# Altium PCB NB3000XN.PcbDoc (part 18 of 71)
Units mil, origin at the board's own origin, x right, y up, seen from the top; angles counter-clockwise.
Board outline 9527.56 x 6929.77 mil, 6 copper layers (Top Layer, GND+SHIELD, MidLayer1, MidLayer2, P2 - 3V3+5V0, Bottom Layer), stack 62.375 mil thick; 832 components, 1027 nets, 4655 pads, 4981 vias.
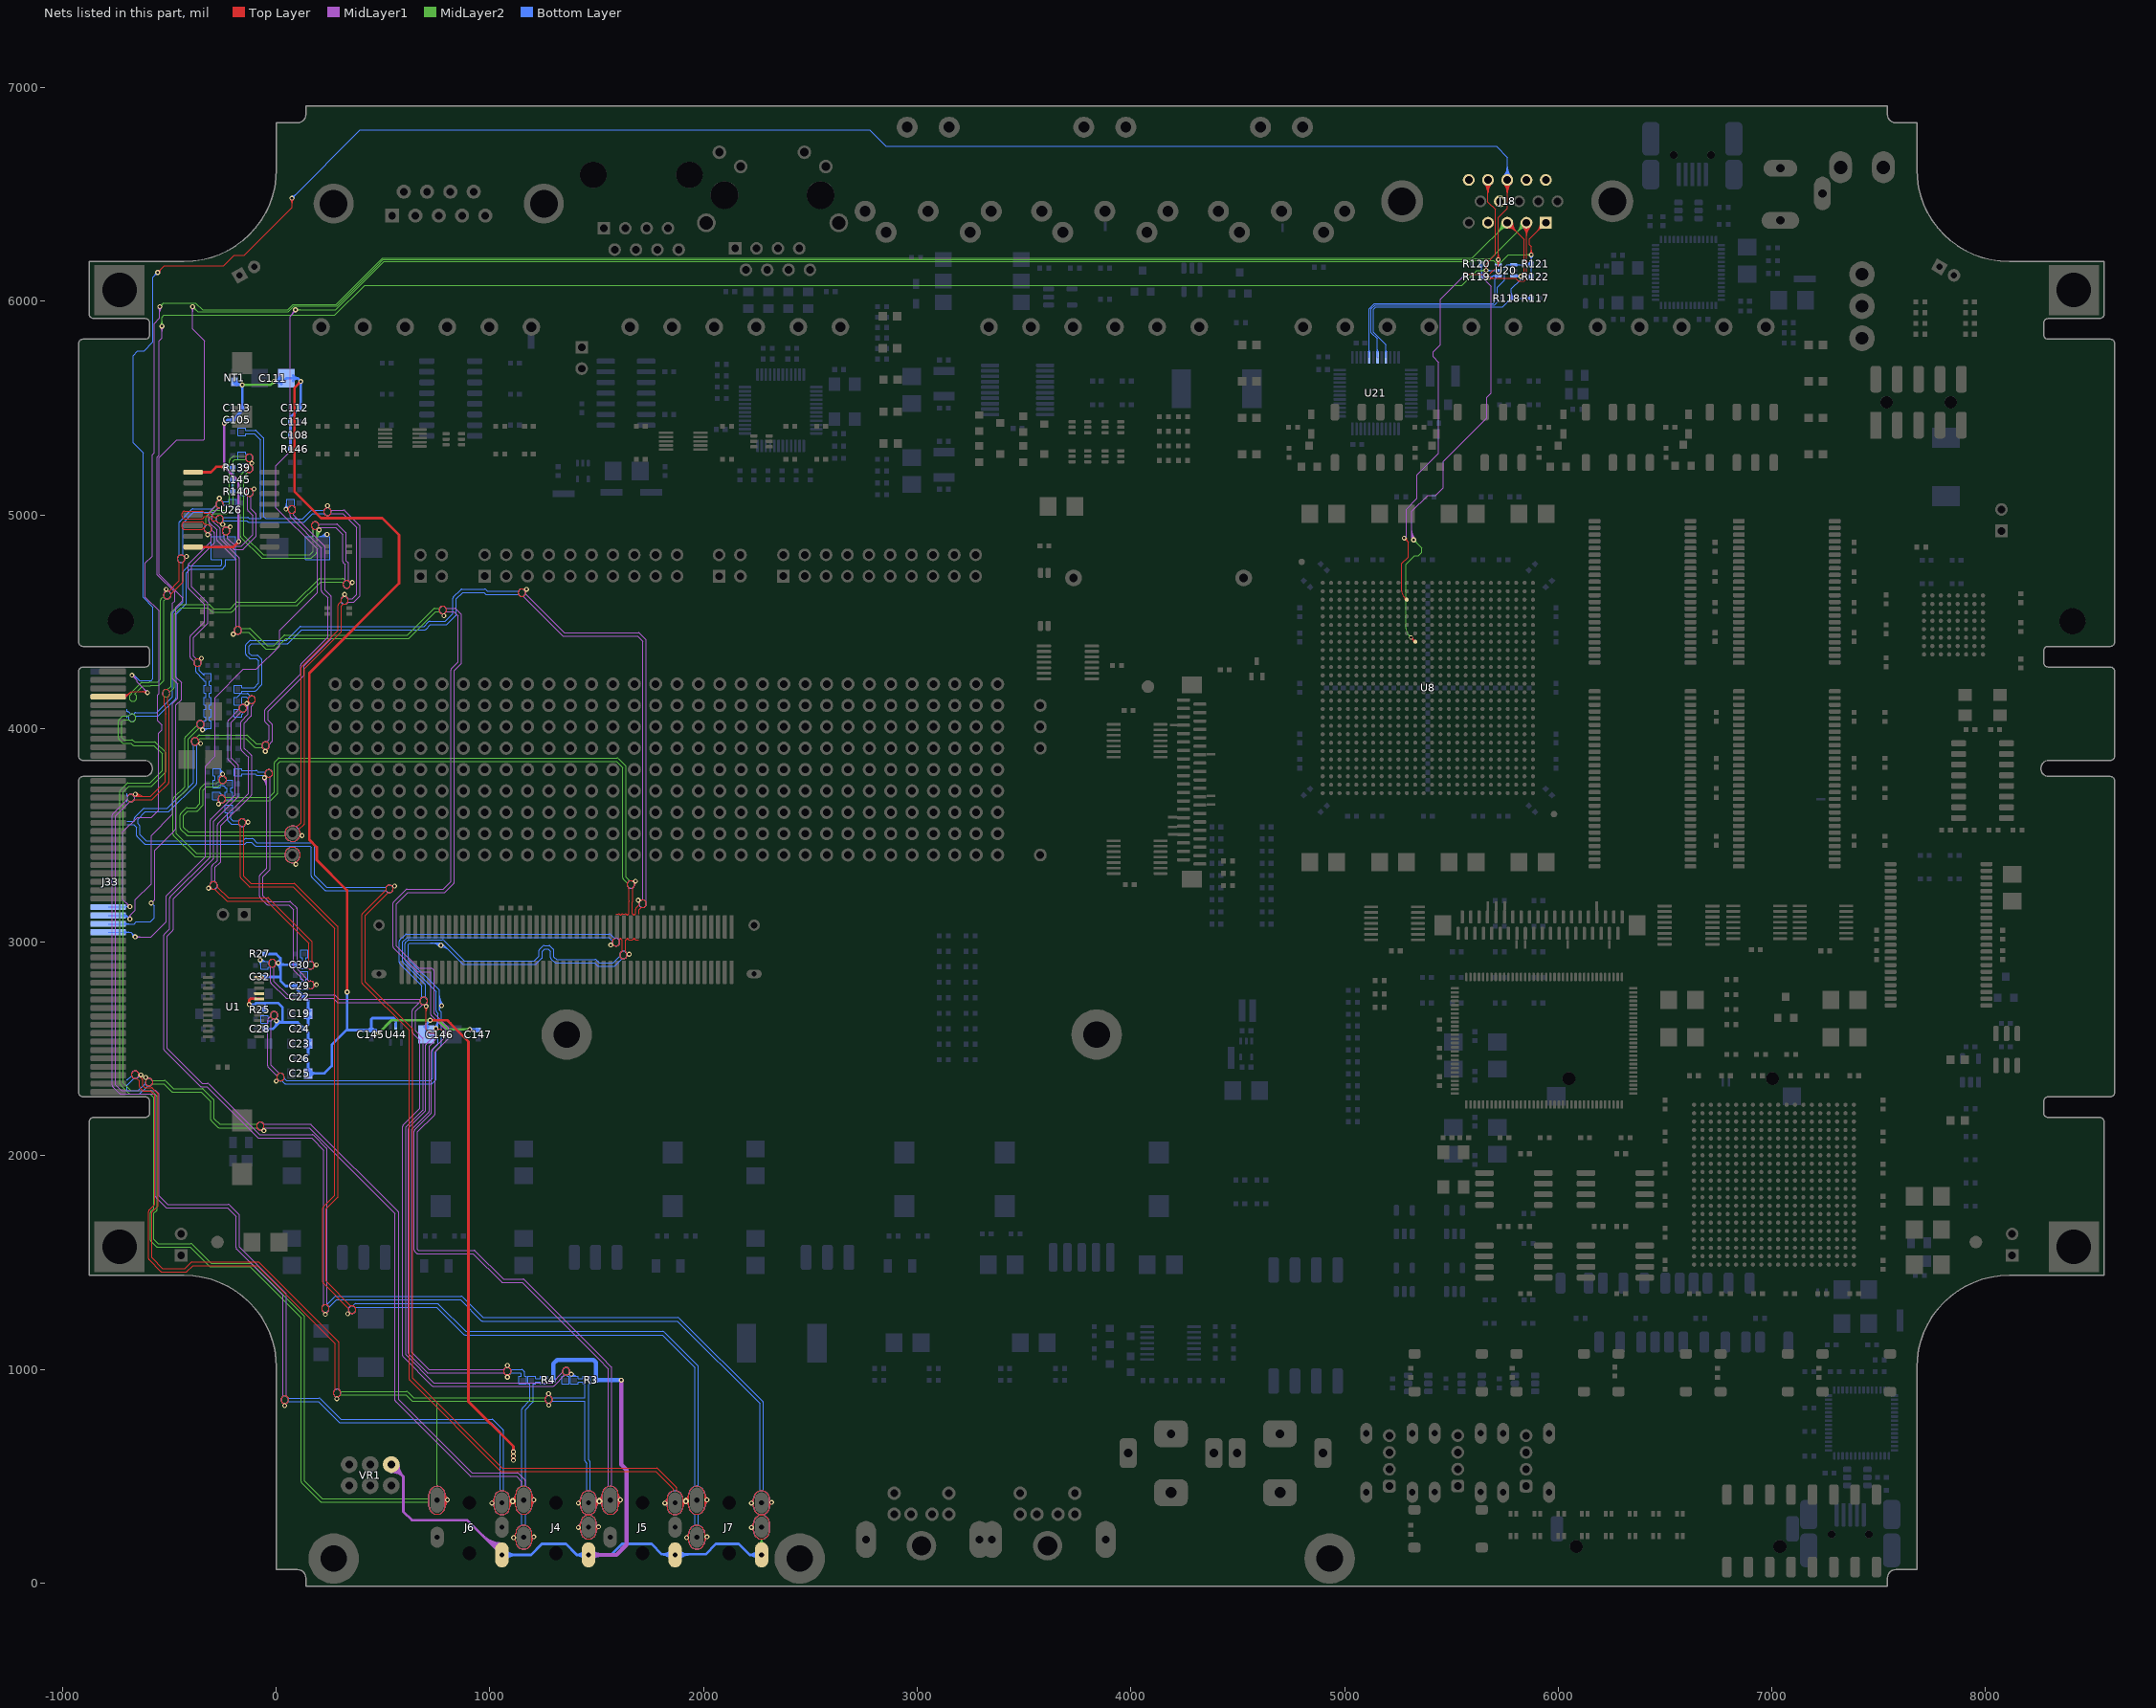
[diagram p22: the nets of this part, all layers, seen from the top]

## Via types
v1: diameter 23, hole 11.81, Top Layer to Bottom Layer, 3672 vias
v2: diameter 26, hole 11.81, Top Layer to Bottom Layer, 461 vias
v3: diameter 19, hole 11.81, Top Layer to Bottom Layer, tented both sides, 396 vias
v4: diameter 23.62, hole 11.81, Top Layer to Bottom Layer, 288 vias
v5: diameter 20, hole 11.81, Top Layer to Bottom Layer, 91 vias
v6: diameter 23, hole 11.81, Top Layer to Bottom Layer, tented both sides, 50 vias
v7: diameter 31, hole 11.81, Top Layer to Bottom Layer, 15 vias
v8: diameter 27.56, hole 11.81, Top Layer to Bottom Layer, tented both sides, 4 vias
v9: diameter 29, hole 11.81, Top Layer to Bottom Layer, 3 vias
v10: diameter 21, hole 11.81, Top Layer to Bottom Layer, 1 vias

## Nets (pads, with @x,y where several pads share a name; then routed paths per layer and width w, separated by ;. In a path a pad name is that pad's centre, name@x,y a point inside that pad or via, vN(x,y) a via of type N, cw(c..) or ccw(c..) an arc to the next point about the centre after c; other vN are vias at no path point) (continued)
ATE.VGA#.BLUE: J18.3 J33.B27 R117.1 R118.2 U20.3 U21.45 | length 12154.1
  Top Layer w4: J18.3@5761.68,6342.44 cw(c5761.68,6280.74) 5805.32,6324.37 cw(c5848.95,6368) J18.3@5787.24,6368 ; J18.3@5761.68,6346.44 cw(c5761.68,6294.39) 5798.49,6331.2 cw(c5835.29,6368) J18.3@5783.24,6368 ; J18.3@5761.68,6350.44 cw(c5761.68,6308.05) 5791.66,6338.02 cw(c5821.64,6368) J18.3@5779.24,6368 ; J18.3@5761.68,6354.44 cw(c5761.68,6321.71) 5784.83,6344.85 cw(c5807.98,6368) J18.3@5775.24,6368 ; J18.3@5761.68,6368 5840,6289.68 5840,6132.18 v1(5824.52,6116.71)
  MidLayer1 w4: v1@-694.31,3166.71 ccw(c-717.24,3166.71) -701.03,3182.93 ccw(c-684.81,3199.14) v1@-684.81,3176.21 ; v1@-690.31,3166.71 ccw(c-703.59,3166.71) -694.2,3176.1 ccw(c-684.81,3185.49) v1@-684.81,3172.21 ; v1(-684.81,3166.71) -718.14,3200.04 -718.14,3516.86 -650,3585 -583.94,3585 -551.48,3617.47 -551.48,3977.46 -534.5,3994.44 -534.5,4015.56 -555,4036.06 -555,4158.5 -549.19,4164.31 -549.19,4551.38 -612.81,4615 -612.81,4775 -580.14,4807.67 -580.14,5281.43 -571.52,5290.05 -571.52,5896.3 -545,5922.82 v4(-545,5975) ; v4@-551.94,5968.06 cw(c-568.69,5951.31) -545,5951.31 cw(c-521.31,5951.31) v4@-538.06,5968.06 ; v4@-549.11,5970.89 cw(c-559.03,5960.97) -545,5960.97 cw(c-530.97,5960.97) v4@-540.89,5970.89
  MidLayer2 w4: v4(-545,5975) -527.46,5992.54 -377.54,5992.54 -344.34,5959.34 53.28,5959.34 79.44,5985.5 280.5,5985.5 497.54,6202.54 5597.54,6202.54 5612.19,6217.19 5761.68,6366.68 J18.3@5761.68,6368 ; v4@-545,5980.81 ccw(c-545,5994.84) -535.08,5984.92 ccw(c-525.16,5975) v4@-539.19,5975 ; v4@-545,5984.81 ccw(c-545,6008.5) -528.25,5991.75 ccw(c-511.5,5975) v4@-535.19,5975 ; 5717.12,6322.12 ccw(c5671.25,6368) J18.3@5736.13,6368 ; 5720.3,6325.3 cw(c5761.68,6283.91) J18.3@5761.68,6342.44 ; 5723.95,6328.95 ccw(c5684.9,6368) J18.3@5740.13,6368 ; 5727.13,6332.13 cw(c5761.68,6297.57) J18.3@5761.68,6346.44 ; 5730.78,6335.78 ccw(c5698.56,6368) J18.3@5744.13,6368 ; 5733.95,6338.95 cw(c5761.68,6311.22) J18.3@5761.68,6350.44 ; 5737.61,6342.61 ccw(c5712.22,6368) J18.3@5748.13,6368 ; 5740.78,6345.78 cw(c5761.68,6324.88) J18.3@5761.68,6354.44
  Bottom Layer w4: J33.B27@-785.98,3164.67 -702.85,3164.67 -700.81,3166.71 ; v1@-693.15,3162.16 ccw(c-700.81,3157.98) -700.81,3166.71 ; v1@-693.15,3171.26 cw(c-700.81,3175.43) -700.81,3166.71 ; v1(-684.81,3166.71) -700.81,3166.71 ; U21.45@5191.38,5763.68 ccw(c5184.56,5770.51) 5194.21,5770.51 ccw(c5203.87,5770.51) U21.45@5197.04,5763.68 ; U21.45@5194.21,5737.32 5194.21,5795.79 5135,5855 5135,5962.37 5146.63,5974 5740.18,5974 R118.2@5781.18,6015 ; 5764.43,5998.25 cw(c5781.18,5981.5) R118.2@5781.18,6005.19 ; 5765.62,5999.44 ccw(c5750.55,6014.51) R118.2@5771.86,6014.51 ; R118.2@5771.26,6005.08 cw(c5781.18,5995.16) R118.2@5781.18,6009.19 ; R118.2@5772.45,6006.27 ccw(c5764.21,6014.51) R118.2@5775.86,6014.51 ; R118.2@5774.59,6022.08 ccw(c5758.68,6037.99) 5781.18,6037.99 ccw(c5803.68,6037.99) R118.2@5787.77,6022.08 ; R118.2@5777.42,6019.25 ccw(c5768.34,6028.33) 5781.18,6028.33 ccw(c5794.02,6028.33) R118.2@5784.94,6019.25 ; R118.2@5784.94,6011.24 cw(c5794.02,6002.16) 5794.02,6015 cw(c5794.02,6027.84) R118.2@5784.94,6018.76 ; R118.2@5787.77,6008.41 cw(c5803.68,5992.5) 5803.68,6015 cw(c5803.68,6037.5) R118.2@5787.77,6021.59 ; U20.3@5792.17,6118.82 v1@5815.19,6118.82 ; U20.3@5796.49,6118.82 cw(c5796.49,6088.68) v1@5817.81,6109.99 ; U20.3@5805.18,6114.67 cw(c5815.19,6104.68) v1@5815.19,6118.82 ; U20.3@5805.18,6122.97 ccw(c5815.19,6132.96) v1@5815.19,6118.82 ; U20.3@5806.15,6118.82 cw(c5806.15,6098.33) v1@5820.64,6112.82 ; U20.3@5806.69,6118.82 ccw(c5806.69,6134.55) v1@5817.81,6123.43 ; v1@5815.19,6118.71 5817.19,6116.71 v1(5824.52,6116.71) 5824.52,6101.71 5781.18,6058.36 R118.2@5781.18,6015 ; R117.1@5867.23,6008.41 ccw(c5851.32,5992.5) 5851.32,6015 ccw(c5851.32,6037.5) R117.1@5867.23,6021.59 ; R117.1@5870.06,6011.24 ccw(c5860.98,6002.16) 5860.98,6015 ccw(c5860.98,6027.84) R117.1@5870.06,6018.76 ; R117.1@5873.82,6015 R118.2@5781.18,6015
ATE.VGA#.GREEN: J18.2 J33.B29 R119.1 R120.2 U20.4 U21.41 | length 12545.8
  Top Layer w4: v1(5672.52,6108.37) 5801.63,6108.37 5815,6095 5840,6095 5851.84,6106.84 J18.2@5851.84,6368 ; v1@5676.41,6104.49 cw(c5685.8,6095.1) 5685.8,6108.37 cw(c5685.8,6121.65) v1@5676.41,6112.26 ; v1@5679.24,6101.66 cw(c5695.46,6085.44) 5695.46,6108.37 cw(c5695.46,6131.31) v1@5679.24,6115.09 ; J18.2@5833.77,6349.93 cw(c5790.14,6306.3) 5851.84,6306.3 cw(c5913.55,6306.3) J18.2@5869.92,6349.93 ; J18.2@5836.6,6352.76 cw(c5799.79,6315.95) 5851.84,6315.95 cw(c5903.89,6315.95) J18.2@5867.09,6352.76 ; J18.2@5839.43,6355.58 cw(c5809.45,6325.61) 5851.84,6325.61 cw(c5894.23,6325.61) J18.2@5864.26,6355.58 ; J18.2@5842.25,6358.41 cw(c5819.11,6335.27) 5851.84,6335.27 cw(c5884.58,6335.27) J18.2@5861.43,6358.41
  MidLayer1 w4: v1(-584.81,3183.37) -569,3199.18 -569,3217.77 -568.98,3429.56 -487.44,3511.1 -468.81,3529.73 -468.81,4109.94 -444,4134.75 -444,4170 -444,4215.25 -468.81,4240.06 -468.81,4566.44 -437.5,4597.75 -437.5,4612.25 -548.14,4722.89 -548.14,5268.17 -464.75,5351.56 -339.03,5351.56 -335.52,5355.08 -335.52,5815.05 -391.48,5871.01 v1(-391.48,5975.04) ; v1@-398.19,5968.32 cw(c-414.41,5952.11) -391.48,5952.11 cw(c-368.54,5952.11) v1@-384.76,5968.32 ; v1@-395.36,5971.15 cw(c-404.75,5961.76) -391.48,5961.76 cw(c-378.2,5961.76) v1@-387.59,5971.15
  MidLayer2 w4: v1@-391.48,5965.54 cw(c-391.48,5942.61) -375.26,5958.82 cw(c-359.04,5975.04) v1@-381.98,5975.04 ; v1@-391.48,5969.54 cw(c-391.48,5956.26) -382.09,5965.65 cw(c-372.7,5975.04) v1@-385.98,5975.04 ; v1(-391.48,5975.04) -367.77,5951.34 56.59,5951.34 82.75,5977.5 283.81,5977.5 472.5,6166.19 500.85,6194.54 5600.85,6194.54 5606.35,6200.04 5683.88,6200.04 J18.2@5851.84,6368 ; J18.2@5826.28,6368 cw(c5764.58,6368) 5808.21,6324.37 cw(c5851.84,6280.74) J18.2@5851.84,6342.44 ; J18.2@5830.28,6368 cw(c5778.23,6368) 5815.04,6331.19 cw(c5851.84,6294.4) J18.2@5851.84,6346.44 ; J18.2@5834.28,6368 cw(c5791.89,6368) 5821.87,6338.02 cw(c5851.84,6308.05) J18.2@5851.84,6350.44 ; J18.2@5838.28,6368 cw(c5805.55,6368) 5828.7,6344.85 cw(c5851.84,6321.71) J18.2@5851.84,6354.44
  Bottom Layer w4: J33.B29@-785.98,3085.93 -663.92,3085.93 -654.72,3095.13 -589.54,3095.13 -570.41,3114.27 -570.41,3168.97 v1(-584.81,3183.37) ; J33.B29@-711.58,3080.43 cw(c-698.3,3067.15) -698.3,3085.93 cw(c-698.3,3104.71) J33.B29@-711.58,3091.43 ; J33.B29@-708.76,3077.6 cw(c-688.65,3057.49) -688.65,3085.93 cw(c-688.65,3114.37) J33.B29@-708.76,3094.26 ; U21.41@5112.64,5763.68 ccw(c5105.82,5770.51) 5115.47,5770.51 ccw(c5125.13,5770.51) U21.41@5118.3,5763.68 ; U21.41@5115.47,5737.32 5115.47,5965.47 5140,5990 5695,5990 5705,6000 5705,6104.49 U20.4@5719.33,6118.82 5718.15,6120 5695,6120 ; R119.1@5634.59,6122.08 ccw(c5618.68,6137.99) 5641.18,6137.99 ccw(c5663.68,6137.99) R119.1@5647.77,6122.08 ; R120.2@5634.59,6167.92 cw(c5618.68,6152.01) 5641.18,6152.01 cw(c5663.68,6152.01) R120.2@5647.77,6167.92 ; R119.1@5637.42,6119.25 ccw(c5628.34,6128.33) 5641.18,6128.33 ccw(c5654.02,6128.33) R119.1@5644.94,6119.25 ; R120.2@5637.42,6170.75 cw(c5628.34,6161.67) 5641.18,6161.67 cw(c5654.02,6161.67) R120.2@5644.94,6170.75 ; R120.2@5641.18,6175 R119.1@5641.18,6115 5647.81,6108.37 v1(5672.52,6108.37) ; R119.1@5642.23,6115.31 ccw(c5656.3,6126.11) 5656.3,6108.37 ; R119.1@5645.4,6117.75 ccw(c5664.41,6132.34) v1@5664.41,6108.37 ; R119.1@5648.57,6120.18 ccw(c5672.52,6138.57) v1(5672.52,6108.37) ; v1@5665.81,6101.66 ccw(c5649.59,6085.44) 5649.59,6108.37 ccw(c5649.59,6131.31) v1@5665.81,6115.09 ; v1@5668.64,6104.49 ccw(c5659.25,6095.1) 5659.25,6108.37 ccw(c5659.25,6121.65) v1@5668.64,6112.26 ; v1@5673.18,6109.72 ccw(c5678.48,6120.63) 5687.06,6112.06 ; v1@5674.93,6113.32 ccw(c5681.08,6125.98) 5691.03,6116.03 ; v1@5676.68,6116.92 ccw(c5683.68,6131.32) 5695,6120 ; 5699.14,6120 ccw(c5699.14,6130.15) U20.4@5706.32,6122.97 ; U20.4@5706.04,6114.97 ccw(c5695,6105.38) 5695,6120 ; v1(5672.52,6108.37) 5683.37,6108.37 5695,6120
ATE.VGA#.HSYNC: J18.13 J33.A4 U8.C11 U20.6 | length 13202.8
  Top Layer w4: J33.A4@-785.98,4148.92 -702.59,4148.92 ; J33.A4@-717.72,4144.75 ccw(c-714.86,4163.57) -701.41,4150.11 ; J33.A4@-717.12,4148.71 ccw(c-713.39,4173.29) -695.81,4155.71 ; J33.A4@-716.52,4152.66 ccw(c-711.92,4183.01) -690.21,4161.3 ; J33.A4@-715.92,4156.62 ccw(c-710.44,4192.73) -684.62,4166.9 ; J33.A4@-715.32,4160.57 ccw(c-708.97,4202.45) -679.02,4172.5 ; J33.A4@-705.55,4146.52 cw(c-702.59,4145.9) -702.59,4148.92 ; J33.A4@-705.55,4151.33 ccw(c-702.59,4151.95) -702.59,4148.92 ; -635.21,4172.5 cw(c-635.21,4135.48) v1@-609.03,4161.66 ; -625.55,4172.5 cw(c-625.55,4145.14) v1@-606.2,4164.49 ; -615.89,4172.5 cw(c-615.89,4154.79) v1@-603.37,4167.31 ; -615.29,4172.5 ccw(c-615.29,4181.35) v1@-609.03,4175.09 ; v1(-602.31,4168.37) -601.48,4168.37 -605.6,4172.5 -679.02,4172.5 -702.59,4148.92 ; v1(-555,6135) -523.29,6166.71 -245.92,6166.71 -197.15,6215.48 -149.52,6215.48 73.52,6438.52 v1(73.52,6482.71) ; v1@-555,6140.5 ccw(c-555,6153.78) -545.61,6144.39 ccw(c-536.22,6135) v1@-549.5,6135 ; v1@-555,6144.5 ccw(c-555,6167.43) -538.78,6151.22 ccw(c-522.57,6135) v1@-545.5,6135 ; v1@66.81,6475.99 cw(c50.59,6459.77) 73.52,6459.77 cw(c96.46,6459.77) v1@80.24,6475.99 ; v1@69.64,6478.82 cw(c60.25,6469.43) 73.52,6469.43 cw(c86.8,6469.43) v1@77.41,6478.82 ; v1@5279.52,4881.87 cw(c5279.52,4858.94) 5295.74,4875.16 cw(c5311.96,4891.37) v1@5289.02,4891.37 ; v1@5279.52,4885.87 cw(c5279.52,4872.6) 5288.91,4881.99 cw(c5298.3,4891.37) v1@5285.02,4891.37 ; v1(5279.52,4891.37) 5298.02,4872.87 5298.02,4803.13 5267.71,4772.82 ; U8.C11@5284.23,4603.39 ccw(c5266.51,4603.39) 5279.04,4615.92 ; U8.C11@5291.57,4610.73 cw(c5291.57,4628.45) 5279.04,4615.92 ; v1(5565.52,6126.37) 5678.52,6126.37 5719.19,6167.04 v1(5719.19,6195.04) ; v1@5569.41,6122.49 cw(c5578.8,6113.1) 5578.8,6126.37 cw(c5578.8,6139.65) v1@5569.41,6130.26 ; v1@5572.24,6119.66 cw(c5588.46,6103.44) 5588.46,6126.37 cw(c5588.46,6149.31) v1@5572.24,6133.09 ; v1@5712.47,6188.32 cw(c5696.26,6172.11) 5719.19,6172.11 cw(c5742.13,6172.11) v1@5725.91,6188.32 ; v1@5712.47,6201.76 ccw(c5696.26,6217.98) 5719.19,6217.98 ccw(c5742.13,6217.98) v1@5725.91,6201.76 ; v1@5715.3,6191.15 cw(c5705.91,6181.76) 5719.19,6181.76 cw(c5732.47,6181.76) v1@5723.08,6191.15 ; v1@5715.3,6198.93 ccw(c5705.91,6208.32) 5719.19,6208.32 ccw(c5732.47,6208.32) v1@5723.08,6198.93 ; v1@5723.52,6199.37 v1(5719.19,6195.04) ; J18.13@5743.61,6549.93 cw(c5699.98,6506.29) 5761.69,6506.29 cw(c5823.39,6506.3) J18.13@5779.76,6549.93 ; J18.13@5746.44,6552.76 cw(c5709.64,6515.95) 5761.69,6515.95 cw(c5813.73,6515.95) J18.13@5776.93,6552.76 ; J18.13@5749.27,6555.58 cw(c5719.29,6525.61) 5761.69,6525.61 cw(c5804.08,6525.61) J18.13@5774.1,6555.58 ; J18.13@5752.1,6558.41 cw(c5728.95,6535.27) 5761.69,6535.27 cw(c5794.42,6535.27) J18.13@5771.27,6558.41 ; J18.13@5761.68,6568 5761.69,6435 5719.19,6392.5 v1(5719.19,6195.04) ; 5267.71,4720 5267.71,4724.74 5267.71,4772.82 ; 5267.71,4720 5267.71,4772.81 ; 5267.71,4720 5267.71,4710 5267.71,4643.27 ccw(c5306.39,4643.27) 5279.04,4615.92
  MidLayer1 w4: v1@-675,4240.5 cw(c-675,4217.56) -658.78,4233.78 cw(c-642.57,4250) v1@-665.5,4250 ; v1@-675,4244.5 cw(c-675,4231.22) -665.61,4240.61 cw(c-656.22,4250) v1@-669.5,4250 ; v1(-675,4250) -650.69,4225.69 -650.69,4217.59 v1@-602.31,4169.21 ; -619.12,4186.02 cw(c-636.76,4168.37) v1@-611.81,4168.37 ; -617.1,4184 ccw(c-602.31,4198.79) v1@-602.31,4177.87 ; -612.29,4179.19 cw(c-623.11,4168.37) v1@-607.81,4168.37 ; -610.27,4177.17 ccw(c-602.31,4185.14) v1@-602.31,4173.87 ; v1(5279.52,4891.37) 5289.52,4901.37 5289.52,5027 5340.19,5077.67 5340.19,5188.73 5440.19,5288.73 5440.19,5582.37 5440.19,5715 5415.19,5740 5415.19,5764.04 5448.52,5797.37 5448.52,6009.37 v1(5565.52,6126.37) ; v1@5556.02,6126.37 cw(c5533.09,6126.37) 5549.31,6110.16 cw(c5565.52,6093.94) v1@5565.52,6116.87 ; v1@5560.02,6126.37 cw(c5546.75,6126.37) 5556.14,6116.99 cw(c5565.52,6107.6) v1@5565.52,6120.87 ; v1@-602.31,4169.21 v1(-602.31,4168.37) -601.48,4168.37 v1@-602.31,4169.21
  Bottom Layer w4: v1@-675,4240.5 cw(c-675,4193.67) -641.88,4226.78 ; v1@-675,4244.5 cw(c-675,4207.32) -648.71,4233.61 ; v1@-675,4248.5 cw(c-675,4220.98) -655.54,4240.44 ; v1(-675,4250) -665.1,4250 -640.1,4225 -585,4225 -576.48,4233.52 -576.48,4567.02 -623,4613.54 -623,5291.69 -670,5338.69 -670,5746.12 -648.12,5768 -618.31,5768 -576.48,5809.84 -576.48,6113.52 v1(-555,6135) ; v1@-675,4252.5 cw(c-675,4234.64) -662.37,4247.27 ; v1@-564.5,6135 cw(c-587.44,6135) -571.22,6118.78 cw(c-555,6102.56) v1@-555,6125.5 ; v1@-560.5,6135 cw(c-573.78,6135) -564.39,6125.61 cw(c-555,6116.22) v1@-555,6129.5 ; v1(73.52,6482.71) 392.82,6802 2776.69,6802 2853.65,6725.04 5709.96,6725.04 5761.68,6673.31 J18.13@5761.68,6568 ; v1@73.52,6488.21 ccw(c73.52,6501.49) 82.91,6492.1 ccw(c92.3,6482.71) v1@79.02,6482.71 ; v1@73.52,6492.21 ccw(c73.52,6515.14) 89.74,6498.93 ccw(c105.96,6482.71) v1@83.02,6482.71 ; v1@5712.47,6188.32 cw(c5695.91,6171.76) U20.6@5719.33,6171.76 ; U20.6@5715.18,6174.15 ccw(c5705.15,6184.18) 5719.33,6184.18 ccw(c5733.51,6184.18) U20.6@5723.49,6174.15 ; v1@5715.3,6191.15 cw(c5705.57,6181.42) 5719.33,6181.42 ; v1(5719.19,6195.04) 5719.33,6194.9 U20.6@5719.33,6170 ; U20.6@5719.33,6172.45 cw(c5741.78,6172.45) v1@5725.91,6188.32 ; 5719.33,6182.11 cw(c5732.12,6182.11) v1@5723.08,6191.15 ; J18.13@5743.61,6586.07 ccw(c5699.98,6629.7) 5761.69,6629.7 ccw(c5823.39,6629.7) J18.13@5779.76,6586.07 ; J18.13@5746.44,6583.24 ccw(c5709.64,6620.05) 5761.68,6620.05 ccw(c5813.73,6620.05) J18.13@5776.93,6583.24 ; J18.13@5749.27,6580.42 ccw(c5719.29,6610.39) 5761.68,6610.39 ccw(c5804.08,6610.39) J18.13@5774.1,6580.42 ; J18.13@5752.1,6577.59 ccw(c5728.95,6600.73) 5761.68,6600.73 ccw(c5794.42,6600.73) J18.13@5771.27,6577.59
ATE.VGA#.ID0: J18.11
ATE.VGA#.ID1/SDA/DDC: J18.12
ATE.VGA#.ID2: J18.4
ATE.VGA#.ID3/SCL/DDC: J18.15
ATE.VGA#.KEY: J18.9
ATE.VGA#.RED: J18.1 J33.B30 R121.2 R122.2 U20.1 U21.43 | length 12038.7
  Top Layer w4: v1@5867.14,6223.76 ccw(c5850.92,6239.98) 5873.86,6239.98 ccw(c5896.79,6239.98) v1@5880.57,6223.76 ; v1@5869.97,6220.93 ccw(c5860.58,6230.32) 5873.86,6230.32 ccw(c5887.14,6230.32) v1@5877.75,6220.93 ; v1(5873.86,6217.04) 5873.86,6256.14 5865,6265 5865,6291 J18.1@5942,6368 ; J18.1@5916.44,6368 cw(c5854.74,6368) 5898.37,6324.37 cw(c5942,6280.74) J18.1@5942,6342.44 ; J18.1@5920.44,6368 cw(c5868.39,6368) 5905.2,6331.2 cw(c5942,6294.39) J18.1@5942,6346.44 ; J18.1@5924.44,6368 cw(c5882.05,6368) 5912.02,6338.02 cw(c5942,6308.05) J18.1@5942,6350.44 ; J18.1@5928.44,6368 cw(c5895.71,6368) 5918.85,6344.85 cw(c5942,6321.71) J18.1@5942,6354.44
  MidLayer1 w4: v1(-659.81,3025.04) -586.02,3025.04 -521,3090.06 -521,3090.31 -515.5,3095.81 -515.5,3216.82 -332,3400.32 -332,3823.31 -285.23,3870.09 -285.23,4006.77 -287,4008.55 -287,4144.87 -153.87,4278 -93.16,4278 15.19,4386.35 15.19,4460.19 192,4637 192,4840.65 -1.48,5034.13 -1.48,5230.39 65.19,5297.06 65.19,5930 v1@92.6,5957.4 ; v1@-655.92,3021.15 cw(c-646.53,3011.76) -646.53,3025.04 cw(c-646.53,3038.32) v1@-655.92,3028.93 ; v1@-653.09,3018.32 cw(c-636.87,3002.11) -636.87,3025.04 cw(c-636.87,3047.98) v1@-653.09,3031.76 ; 70.11,5934.92 ccw(c45.03,5960) v1@80.5,5960 ; 76.94,5941.75 ccw(c58.69,5960) v1@84.5,5960 ; 82.64,5947.45 cw(c90,5940.1) v1@90,5950.5 ; 83.77,5948.58 ccw(c72.35,5960) v1@88.5,5960
  MidLayer2 w4: v1(90,5960) 277.63,5960 504.17,6186.54 5604.17,6186.54 5609.34,6191.71 5697.77,6191.71 5711.94,6177.54 5726.44,6177.54 5765.94,6217.04 v1(5873.86,6217.04) ; v1@93.89,5956.11 cw(c103.28,5946.72) 103.28,5960 cw(c103.28,5973.28) v1@93.89,5963.89 ; v1@96.72,5953.28 cw(c112.93,5937.06) 112.93,5960 cw(c112.93,5982.93) v1@96.72,5966.72 ; v1@5867.14,6210.32 ccw(c5850.92,6194.11) 5850.92,6217.04 ccw(c5850.92,6239.98) v1@5867.14,6223.76 ; v1@5869.97,6213.15 ccw(c5860.58,6203.76) 5860.58,6217.04 ccw(c5860.58,6230.32) v1@5869.97,6220.93
  Bottom Layer w4: J33.B30@-785.98,3046.56 -681.33,3046.56 v1(-659.81,3025.04) ; J33.B30@-711.58,3041.06 cw(c-698.3,3027.78) -698.3,3046.56 cw(c-698.3,3065.34) J33.B30@-711.58,3052.06 ; J33.B30@-708.76,3038.23 cw(c-688.65,3018.12) -688.65,3046.56 cw(c-688.65,3075) J33.B30@-708.76,3054.89 ; v1@-669.31,3025.04 ccw(c-692.24,3025.04) -676.03,3041.26 ccw(c-659.81,3057.48) v1@-659.81,3034.54 ; v1@-665.31,3025.04 ccw(c-678.59,3025.04) -669.2,3034.43 ccw(c-659.81,3043.82) v1@-659.81,3030.54 ; 5152.89,5775.23 ccw(c5169.22,5775.23) U21.43@5157.67,5763.68 ; U21.43@5154.84,5737.32 5152.89,5739.28 5152.89,5825 5125,5852.89 5125,5963.69 5143.31,5982 5702,5982 5715,5995 5715,6065 5750,6100 5750,6160 5760,6170 U20.1@5792.17,6170 5868.82,6170 R121.2@5873.82,6175 ; U20.1@5779.16,6165.85 ccw(c5769.13,6155.82) 5769.13,6170 ccw(c5769.13,6184.18) U20.1@5779.16,6174.15 ; U20.1@5805.18,6165.85 cw(c5815.21,6155.82) 5815.21,6170 cw(c5815.21,6184.18) U20.1@5805.18,6174.15 ; 5840.44,6170 ccw(c5840.44,6207.89) R121.2@5867.23,6181.1 ; 5850.09,6170 ccw(c5850.09,6198.23) R121.2@5870.06,6178.27 ; 5859.75,6170 ccw(c5859.75,6188.57) R121.2@5872.89,6175.44 ; 5862.2,6170 cw(c5862.2,6162.89) 5867.23,6167.92 cw(c5851.32,6152.01) 5873.82,6152.01 cw(c5896.32,6152.01) R121.2@5880.41,6167.92 ; v1@5867.14,6210.32 cw(c5850.92,6194.11) 5873.86,6194.11 cw(c5896.79,6194.11) v1@5880.57,6210.32 ; R122.2@5867.23,6122.08 ccw(c5851.32,6137.99) 5873.82,6137.99 ccw(c5896.32,6137.99) R122.2@5880.41,6122.08 ; R121.2@5867.23,6182.08 ccw(c5851.23,6198.08) 5873.86,6198.08 ; v1@5869.97,6213.15 cw(c5860.58,6203.76) 5873.86,6203.76 cw(c5887.14,6203.76) v1@5877.75,6213.15 ; R122.2@5870.06,6119.25 ccw(c5860.98,6128.33) 5873.82,6128.33 ccw(c5886.66,6128.33) R122.2@5877.58,6119.25 ; R121.2@5870.06,6170.75 cw(c5860.98,6161.67) 5873.82,6161.67 cw(c5886.66,6161.67) R121.2@5877.58,6170.75 ; R121.2@5870.06,6179.25 ccw(c5860.89,6188.43) 5873.86,6188.43 ; R122.2@5873.82,6115 R121.2@5873.82,6175 ; 5873.86,6188.24 ccw(c5886.57,6188.24) R121.2@5877.58,6179.25 ; 5873.86,6197.9 ccw(c5896.22,6197.9) R121.2@5880.41,6182.08 ; v1(5873.86,6217.04) 5873.86,6175.04 R121.2@5873.82,6175
ATE.VGA#.VSYNC: J18.14 J33.B28 U8.H12 U20.5 | length 13007.6
  Top Layer w4: v3(5311.26,4426.22) U8.H12@5330.94,4406.54 ; U8.H12@5323.44,4406.54 ccw(c5305.34,4406.54) 5318.14,4419.34 ccw(c5330.94,4432.14) U8.H12@5330.94,4414.04 ; U8.H12@5323.6,4406.54 ccw(c5305.88,4406.54) 5318.41,4419.07 ccw(c5330.94,4431.6) U8.H12@5330.94,4413.88 ; J18.14@5653.45,6549.93 cw(c5609.82,6506.29) 5671.53,6506.29 cw(c5733.23,6506.3) J18.14@5689.6,6549.93 ; v1@5656.14,6151.43 ccw(c5639.92,6167.64) 5662.86,6167.64 ccw(c5685.79,6167.64) v1@5669.57,6151.43 ; J18.14@5656.28,6552.76 cw(c5619.48,6515.95) 5671.53,6515.95 cw(c5723.57,6515.95) J18.14@5686.77,6552.76 ; v1@5658.97,6148.6 ccw(c5649.58,6157.99) 5662.86,6157.99 ccw(c5676.14,6157.99) v1@5666.75,6148.6 ; J18.14@5659.11,6555.58 cw(c5629.13,6525.61) 5671.53,6525.61 cw(c5713.92,6525.61) J18.14@5683.94,6555.58 ; J18.14@5661.94,6558.41 cw(c5638.79,6535.26) 5671.53,6535.26 cw(c5704.26,6535.27) J18.14@5681.12,6558.41 ; v1(5662.86,6144.71) 5662.86,6175 5706.86,6219 5706.86,6429.71 5671.53,6465.04 J18.14@5671.53,6568 ; 5324.06,4413.42 cw(c5336.87,4426.22) 5318.76,4426.22 ccw(c5336.87,4426.22) 5324.06,4413.42 ; 5324.06,4413.42 ccw(c5311.26,4400.61) 5311.26,4418.72 cw(c5311.26,4400.61) 5324.06,4413.42
  MidLayer1 w4: v1@-689.65,3116.55 ccw(c-694.68,3125.04) -684.81,3125.04 ; v1(-684.81,3108.37) -684.81,3125.04 ; v1@-679.97,3116.55 cw(c-674.94,3125.04) -684.81,3125.04 ; v1@-541.53,5876.66 cw(c-557.74,5860.44) -534.81,5860.44 cw(c-511.87,5860.44) v1@-528.09,5876.66 ; v1@-538.7,5879.49 cw(c-548.09,5870.1) -534.81,5870.1 cw(c-521.53,5870.1) v1@-530.92,5879.49 ; v1(-534.81,5883.37) -534.81,5827.75 -544,5818.56 -547.52,5815.05 -547.52,5280.11 -556.14,5271.48 -556.14,4719.58 -475,4638.43 -475,4596.31 -484.81,4586.5 -484.81,4233.43 -460,4208.62 -460,4141.38 -484.81,4116.57 -484.81,3600.04 -585,3499.85 -585,3272.79 -659.81,3197.98 -659.81,3150.04 -684.81,3125.04 ; 5315.19,4897.46 ccw(c5337.61,4897.46) v1@5321.76,4881.61 ; 5315.19,4907.12 ccw(c5347.27,4907.12) v1@5324.58,4884.44 ; 5315.19,4916.77 ccw(c5356.92,4916.77) v1@5327.41,4887.26 ; 5315.19,4926.43 ccw(c5366.58,4926.43) v1@5330.24,4890.09 ; v1(5323.52,4883.37) 5315.19,4891.71 5315.19,5016.71 5390.19,5091.71 5426.71,5091.71 5462.5,5127.5 5462.5,5250.33 5666.19,5454.02 5666.19,5551.45 5686,5571.26 5686,6069 5650,6105 5650,6131.85 v1(5662.86,6144.71)
  MidLayer2 w4: v1@-541.53,5890.09 ccw(c-557.74,5906.31) -534.81,5906.31 ccw(c-511.87,5906.31) v1@-528.09,5890.09 ; v1@-538.7,5887.26 ccw(c-548.09,5896.65) -534.81,5896.65 ccw(c-521.53,5896.65) v1@-530.92,5887.26 ; v1(-534.81,5883.37) -534.81,5925.19 -524.66,5935.34 78.6,5935.34 79.44,5934.5 274.76,5934.5 415.3,6075.04 5550,6075.04 5619.67,6144.71 v1(5662.86,6144.71) ; 5287.4,4699.16 5287.4,4640.9 ; v3@5303.79,4426.87 ccw(c5285.75,4428.45) 5299.62,4440.09 ; v3@5311.91,4433.69 cw(c5313.49,4451.73) 5299.62,4440.09 ; v1@5323.52,4873.87 cw(c5323.52,4850.94) 5339.74,4867.16 cw(c5355.96,4883.37) v1@5333.02,4883.37 ; v1@5323.52,4877.87 cw(c5323.52,4864.6) 5332.91,4873.99 cw(c5342.3,4883.37) v1@5329.02,4883.37 ; v1(5323.52,4883.37) 5362.52,4844.37 5362.52,4827.52 5362.5,4825 5347.07,4809.56 5327.03,4809.56 5287.4,4769.93 5287.4,4720 5287.4,4710 5287.4,4640.9 ; v1@5656.14,6137.99 ccw(c5639.92,6121.77) 5639.92,6144.71 ccw(c5639.92,6167.64) v1@5656.14,6151.43 ; v1@5658.97,6140.82 ccw(c5649.58,6131.43) 5649.58,6144.71 ccw(c5649.58,6157.99) v1@5658.97,6148.6 ; 5287.4,4640.9 5287.4,4582.64 5287.4,4563.22 5287.4,4489.1 5287.4,4469.6 ccw(c5329.13,4469.6) 5299.62,4440.09
  Bottom Layer w4: J33.B28@-785.98,3125.3 -701.74,3125.3 ; J33.B28@-717.65,3129.48 cw(c-714.82,3108.65) -699.95,3123.52 ; J33.B28@-717.11,3125.52 cw(c-713.45,3098.61) -694.25,3117.81 ; J33.B28@-716.57,3121.56 cw(c-712.09,3088.57) v1@-688.55,3112.11 ; J33.B28@-716.04,3117.59 cw(c-710.72,3078.53) v1@-682.84,3106.41 ; J33.B28@-705.71,3122.26 cw(c-701.74,3121.19) -701.74,3125.3 ; J33.B28@-705.71,3128.35 ccw(c-701.74,3129.41) -701.74,3125.3 ; v1@-694.31,3108.37 ccw(c-717.24,3108.37) -701.03,3124.59 ccw(c-684.81,3140.81) v1@-684.81,3117.87 ; v1@-690.31,3108.37 ccw(c-703.59,3108.37) -694.2,3117.76 ccw(c-684.81,3127.15) v1@-684.81,3113.87 ; v1(-684.81,3108.37) -701.74,3125.3 ; v1(5662.86,6144.71) 5678.86,6144.71 ; v1@5671.2,6140.16 cw(c5678.86,6135.98) 5678.86,6144.71 ; v1@5671.2,6149.26 ccw(c5678.86,6153.43) 5678.86,6144.71 ; U20.5@5706.32,6140.26 ccw(c5696.29,6130.23) 5696.29,6144.41 ccw(c5696.29,6158.59) U20.5@5706.32,6148.56 ; U20.5@5719.33,6144.41 5679.16,6144.41 5678.86,6144.71
AUDIO_CODEC.MUTEA: U1.21
AUDIO_CODEC.MUTEB: U1.24
AUGND: C19.2 C22.2 C23.2 C24.1 C25.2 C26.2 C28.2 C29.2 C30.2 C32.2 C105.1 C108.2 C111.2 C112.1 C113.1 C114.1 C145.1 C146.2 C147.1 J4.1 J5.1 J6.1 J7.1 NT1.1 R3.1 R4.1 R25.1 R27.1 R139.1 R140.1 R145.1 R146.2 U1.20 U26.1 U26.8 U44.2 VR1.1 | length 223427.7
  Top Layer w4: -692.37,3662.63 ccw(c-680,3675) -664.44,3667 -584.81,3667 ; -692.37,3687.37 cw(c-680,3675) -664.44,3683 -588.12,3683 -566.63,3704.49 ; v1@-664.1,3688.4 ccw(c-651.05,3701.45) -651.05,3683 ; v1@-661.27,3691.23 ccw(c-641.39,3711.11) -641.39,3683 ; v1@-658.44,3694.06 ccw(c-631.74,3720.76) -631.74,3683 ; v1@-655.61,3696.89 ccw(c-622.08,3730.42) -622.08,3683 ; v1@-652.78,3699.72 ccw(c-612.42,3740.08) -612.42,3683 ; -570.04,3701.09 -566.63,3704.5 ; -555.32,3693.18 -558.73,3689.77 ; -518,3795 -518,3753.12 -566.63,3704.5 ; -517.81,3796.73 -517.81,4068.27 cw(c-510,4070) -517.81,4071.73 -517.81,4101.69 -520.66,4104.53 ; -502,3793.27 -502,3749.81 ; -501.81,3795 -501.81,4070.19 -501.81,4105 ; -338.09,4941.77 cw(c-349.76,4944.09) -349.76,4932.19 -428.5,4932.19 cw(c-428.5,4944.09) -440.41,4944.09 -440.41,4955.91 cw(c-428.5,4955.91) -428.5,4967.81 -349.76,4967.81 cw(c-349.76,4955.91) -338.04,4958 -335,4958 ; -336.66,4940.35 ccw(c-320,4935) -302.5,4935 ccw(c-320,4935) -325.35,4951.66 -329.34,4955.66 ; v1@695.28,2693.28 cw(c679.06,2677.06) 702,2677.06 cw(c724.93,2677.06) v1@708.72,2693.28 ; v1@698.11,2696.11 cw(c688.72,2686.72) 702,2686.72 cw(c715.28,2686.72) v1@705.89,2696.11 ; v1(702,2700) 702,2593 720,2575 745,2575 ; 790.92,358.84 cw(c815.82,358.84) v1@804.98,381.26 ; 790.92,365.22 cw(c812.74,365.22) v1@803.24,384.86 ; 790.92,371.59 cw(c809.66,371.59) v1@801.5,388.46 ; 790.92,377.97 cw(c806.58,377.97) v1@799.76,392.06 ; 790.92,399.67 ccw(c803.67,399.67) v1@800.16,387.41 ; 790.92,404.98 ccw(c805.2,404.98) v1@801.26,391.25 ; 790.92,410.28 ccw(c806.72,410.28) v1@802.37,395.1 ; v1@803.47,398.94 cw(c808.24,415.59) 790.92,415.59 ; v1@1009.14,375.94 ccw(c1009.11,385.91) 1019.08,385.91 ; v1@1009.13,379.94 ccw(c1009.1,389.92) 1019.08,389.92 ; v1@1009.12,383.94 ccw(c1009.08,393.94) 1019.08,393.94 ; v1@1009.16,371.94 ccw(c1009.12,381.9) 1019.08,381.9 ; 1094.07,359.39 cw(c1109.48,359.39) v9@1108.25,374.75 ; 1094.07,363.72 cw(c1109.13,363.72) v9@1107.93,378.73 ; 1094.07,368.05 cw(c1108.79,368.05) v9@1107.61,382.72 ; 1094.07,372.39 cw(c1108.44,372.39) v9@1107.3,386.71 ; 1094.07,376.72 cw(c1108.09,376.72) v9@1106.98,390.7 ; v9@1104.81,395.41 ccw(c1100.24,415.59) 1120.93,415.59 ; v9@1105.7,391.51 ccw(c1101.37,410.58) 1120.93,410.58 ; v9@1106.58,387.61 ccw(c1102.51,405.57) 1120.93,405.57 ; v9@1107.4,374.72 cw(c1107.13,360.92) 1120.93,360.92 ; v9@1107.48,378.72 cw(c1107.21,365) 1120.93,365 ; v9@1107.46,383.71 ccw(c1103.64,400.57) 1120.93,400.57 ; v9@1107.56,382.72 cw(c1107.29,369.09) 1120.93,369.09 ; v9@1107.64,386.72 cw(c1107.37,373.17) 1120.93,373.17 ; v9@1107.73,390.72 cw(c1107.46,377.25) 1120.93,377.25 ; v9@1108.35,379.81 ccw(c1104.78,395.56) 1120.93,395.56 ; v9@1109.23,375.91 ccw(c1105.91,390.55) 1120.93,390.55 ; v1@1110.99,214.52 ccw(c1110.96,224.49) 1120.93,224.49 ; v1@1110.98,218.52 ccw(c1110.95,228.51) 1120.93,228.51 ; v1@1110.97,222.52 ccw(c1110.93,232.52) 1120.93,232.52 ; v1@1111.01,210.52 ccw(c1110.97,220.48) 1120.93,220.48 ; 1195.92,199.21 cw(c1207.92,199.21) v1@1206.5,211.12 ; 1195.92,203.71 cw(c1207.38,203.71) v1@1206.03,215.09 ; 1195.92,208.22 cw(c1206.85,208.22) v1@1205.56,219.07 ; 1195.92,358.84 cw(c1220.82,358.84) v1@1209.98,381.26 ; 1195.92,365.22 cw(c1217.74,365.22) v1@1208.24,384.86 ; 1195.92,371.59 cw(c1214.66,371.59) v1@1206.5,388.46 ; 1195.92,377.97 cw(c1211.58,377.97) v1@1204.76,392.06 ; 1195.92,399.67 ccw(c1208.67,399.67) v1@1205.16,387.41 ; 1195.92,404.98 ccw(c1210.2,404.98) v1@1206.26,391.25 ; 1195.92,410.28 ccw(c1211.72,410.28) v1@1207.37,395.1 ; v1@1208.47,398.94 cw(c1213.24,415.59) 1195.92,415.59 ; v1@1414.14,261.77 ccw(c1414.11,271.74) 1424.08,271.74 ; v1@1414.13,265.77 ccw(c1414.1,275.75) 1424.08,275.75 ; v1@1414.12,269.77 ccw(c1414.08,279.76) 1424.08,279.76 ; v1@1414.14,375.94 ccw(c1414.11,385.91) 1424.08,385.91 ; v1@1414.13,379.94 ccw(c1414.1,389.92) 1424.08,389.92 ; v1@1414.12,383.94 ccw(c1414.08,393.94) 1424.08,393.94 ; v1@1414.16,257.77 ccw(c1414.12,267.72) 1424.08,267.72 ; v1@1414.16,371.94 ccw(c1414.12,381.9) 1424.08,381.9 ; 1499.07,246.45 cw(c1511.07,246.45) v1@1509.65,258.37 ; 1499.07,250.96 cw(c1510.53,250.96) v1@1509.18,262.34 ; 1499.07,255.46 cw(c1510,255.46) v1@1508.7,266.31 ; 1499.07,359.39 cw(c1514.48,359.39) v9@1513.25,374.75 ; 1499.07,363.72 cw(c1514.13,363.72) v9@1512.93,378.73 ; 1499.07,368.05 cw(c1513.79,368.05) v9@1512.61,382.72 ; 1499.07,372.39 cw(c1513.44,372.39) v9@1512.3,386.71 ; 1499.07,376.72 cw(c1513.09,376.72) v9@1511.98,390.7 ; v9@1509.81,395.41 ccw(c1505.24,415.59) 1525.93,415.59 ; v9@1510.7,391.51 ccw(c1506.37,410.58) 1525.93,410.58 ; v9@1511.58,387.61 ccw(c1507.51,405.57) 1525.93,405.57 ; v9@1512.4,374.72 cw(c1512.13,360.92) 1525.93,360.92 ; v9@1512.48,378.72 cw(c1512.21,365) 1525.93,365 ; v9@1512.46,383.71 ccw(c1508.64,400.57) 1525.93,400.57 ; v9@1512.56,382.72 cw(c1512.29,369.09) 1525.93,369.09 ; v9@1512.64,386.72 cw(c1512.37,373.17) 1525.93,373.17 ; v9@1512.73,390.72 cw(c1512.46,377.25) 1525.93,377.25 ; v9@1513.35,379.81 ccw(c1509.78,395.56) 1525.93,395.56 ; v9@1514.23,375.91 ccw(c1510.91,390.55) 1525.93,390.55 ; 1581.84,3015.48 ccw(c1590,3000) 1607.5,3000 ccw(c1590,3000) 1603.89,3010.65 ; 1590.89,3132.97 1600.89,3132.97 cw(c1600.89,3121.97) 1611.64,3124.31 cw(c1622.39,3121.97) 1622.39,3132.97 1632.39,3132.97 cw(c1632.39,3121.97) 1643.13,3124.31 cw(c1653.88,3121.97) 1650.88,3132.55 1650.88,3189.4 ; 1600.92,358.84 cw(c1625.82,358.84) v1@1614.98,381.26 ; 1600.92,365.22 cw(c1622.74,365.22) v1@1613.24,384.86 ; 1600.92,371.59 cw(c1619.66,371.59) v1@1611.5,388.46 ; 1600.92,377.97 cw(c1616.58,377.97) v1@1609.76,392.06 ; 1600.92,399.67 ccw(c1613.67,399.67) v1@1610.16,387.41 ; 1600.92,404.98 ccw(c1615.2,404.98) v1@1611.26,391.25 ; 1600.92,410.28 ccw(c1616.72,410.28) v1@1612.37,395.1 ; 1603.89,3011.15 ccw(c1600.89,3021.73) 1611.64,3019.39 ccw(c1622.39,3021.73) 1619.39,3011.15 1619.39,2956.57 ccw(c1625,2940) 1642.5,2940 ccw(c1625,2940) 1635.39,2954.09 1635.39,3011.15 ccw(c1632.39,3021.73) 1643.13,3019.39 ccw(c1653.88,3021.73) 1653.88,3010.73 1663.88,3010.73 ccw(c1663.88,3021.73) 1674.63,3019.39 ccw(c1685.38,3021.73) 1685.38,3010.73 1695.38,3010.73 ; v1@1613.47,398.94 cw(c1618.24,415.59) 1600.92,415.59 ; 1698.38,3132.55 1698.38,3151.87 1709.84,3163.34 ccw(c1715.19,3180) 1732.69,3180 ccw(c1715.19,3180) 1698.53,3174.65 1684.72,3160.84 ; v1@1819.14,375.94 ccw(c1819.11,385.91) 1829.08,385.91 ; v1@1819.13,379.94 ccw(c1819.1,389.92) 1829.08,389.92 ; v1@1819.12,383.94 ccw(c1819.08,393.94) 1829.08,393.94 ; v1@1819.16,371.94 ccw(c1819.12,381.9) 1829.08,381.9 ; 1904.07,359.39 cw(c1919.48,359.39) v9@1918.25,374.75 ; 1904.07,363.72 cw(c1919.13,363.72) v9@1917.93,378.73 ; 1904.07,368.05 cw(c1918.79,368.05) v9@1917.61,382.72 ; 1904.07,372.39 cw(c1918.44,372.39) v9@1917.3,386.71 ; 1904.07,376.72 cw(c1918.09,376.72) v9@1916.98,390.7 ; v9@1914.81,395.41 ccw(c1910.24,415.59) 1930.93,415.59 ; v9@1915.7,391.51 ccw(c1911.37,410.58) 1930.93,410.58 ; v9@1916.58,387.61 ccw(c1912.51,405.57) 1930.93,405.57 ; v9@1917.4,374.72 cw(c1917.13,360.92) 1930.93,360.92 ; v9@1917.48,378.72 cw(c1917.21,365) 1930.93,365 ; v9@1917.46,383.71 ccw(c1913.64,400.57) 1930.93,400.57 ; v9@1917.56,382.72 cw(c1917.29,369.09) 1930.93,369.09 ; v9@1917.64,386.72 cw(c1917.37,373.17) 1930.93,373.17 ; v9@1917.73,390.72 cw(c1917.46,377.25) 1930.93,377.25 ; v9@1918.35,379.81 ccw(c1914.78,395.56) 1930.93,395.56 ; v9@1919.23,375.91 ccw(c1915.91,390.55) 1930.93,390.55 ; v1@1920.99,214.52 ccw(c1920.96,224.49) 1930.93,224.49 ; v1@1920.98,218.52 ccw(c1920.95,228.51) 1930.93,228.51 ; v1@1920.97,222.52 ccw(c1920.93,232.52) 1930.93,232.52 ; v1@1921.01,210.52 ccw(c1920.97,220.48) 1930.93,220.48 ; 2005.92,199.21 cw(c2017.92,199.21) v1@2016.5,211.12 ; 2005.92,203.71 cw(c2017.38,203.71) v1@2016.03,215.09 ; 2005.92,208.22 cw(c2016.85,208.22) v1@2015.56,219.07 ; 2005.92,358.84 cw(c2030.82,358.84) v1@2019.98,381.26 ; 2005.92,365.22 cw(c2027.74,365.22) v1@2018.24,384.86 ; 2005.92,371.59 cw(c2024.66,371.59) v1@2016.5,388.46 ; 2005.92,377.97 cw(c2021.58,377.97) v1@2014.76,392.06 ; 2005.92,399.67 ccw(c2018.67,399.67) v1@2015.16,387.41 ; 2005.92,404.98 ccw(c2020.2,404.98) v1@2016.26,391.25 ; 2005.92,410.28 ccw(c2021.72,410.28) v1@2017.37,395.1 ; v1@2018.47,398.94 cw(c2023.24,415.59) 2005.92,415.59 ; v1@2224.14,261.77 ccw(c2224.11,271.74) 2234.08,271.74 ; v1@2224.13,265.77 ccw(c2224.1,275.75) 2234.08,275.75 ; v1@2224.12,269.77 ccw(c2224.08,279.76) 2234.08,279.76 ; v1@2224.14,375.94 ccw(c2224.11,385.91) 2234.08,385.91 ; v1@2224.13,379.94 ccw(c2224.1,389.92) 2234.08,389.92 ; v1@2224.12,383.94 ccw(c2224.08,393.94) 2234.08,393.94 ; v1@2224.16,257.77 ccw(c2224.12,267.72) 2234.08,267.72 ; v1@2224.16,371.94 ccw(c2224.12,381.9) 2234.08,381.9 ; 2309.07,360.63 cw(c2321.07,360.63) v1@2319.65,372.54 ; 2309.07,365.13 cw(c2320.53,365.13) v1@2319.18,376.51 ; 2309.07,369.63 cw(c2320,369.63) v1@2318.7,380.48 ; -641,2325.62 ccw(c-633,2325.62) -638.66,2319.97 ; -641,2325.62 ccw(c-633,2325.62) -638.66,2319.97 ; -641,2325.62 -641,2349.69 -654.65,2363.34 cw(c-660,2380) -642.5,2380 cw(c-660,2380) -643.34,2374.65 -627.34,2358.66 ; -638.66,2319.97 -624.53,2305.84 ; -627.34,2358.66 cw(c-633,2353) -625,2353 ; -627.34,2358.66 cw(c-633,2353) -625,2353 ; -625,2353 -625,2328.94 -615.56,2319.5 -585,2319.5 ; -624.53,2305.84 ccw(c-618.88,2311.5) -618.88,2303.5 ; -624.53,2305.84 ccw(c-618.88,2311.5) -618.88,2303.5 ; -618.88,2303.5 -588.31,2303.5 -568,2283.19 -568,1773.31 -595.66,1745.66 ; -598,1520 ccw(c-590,1520) -595.66,1514.34 ; -598,1520 ccw(c-590,1520) -595.66,1514.34 ; -598,1520 -598,1740 ; -598,1740 cw(c-590,1740) -595.66,1745.66 ; -598,1740 cw(c-590,1740) -595.66,1745.66 ; -595.66,1514.34 -540.36,1459.05 ; -585,2319.5 cw(c-585,2311.5) -579.34,2317.16 ; -585,2319.5 cw(c-585,2311.5) -579.34,2317.16 ; -584.81,3667 ccw(c-584.81,3675) -579.15,3669.34 ; -584.81,3667 ccw(c-584.81,3675) -579.15,3669.34 ; -579.34,2317.16 -554.34,2292.16 ; -579.15,3669.34 -558.73,3689.77 ; -558.72,3689.77 -504.34,3744.15 ; -554.34,1764.34 ccw(c-560,1770) -552,1770 ; -554.34,1764.34 ccw(c-560,1770) -552,1770 ; -554.34,1764.34 -582,1736.69 -582,1523.31 -531.39,1472.71 -426.23,1472.71 -398.28,1500.66 ; -554.34,2292.16 cw(c-560,2286.5) -552,2286.5 ; -554.34,2292.16 cw(c-560,2286.5) -552,2286.5 ; -552,1770 -552,2286.5 ; -540.36,1459.05 ccw(c-534.71,1464.71) -534.71,1456.71 ; -540.36,1459.05 ccw(c-534.71,1464.71) -534.71,1456.71 ; -534.71,1456.71 -422.92,1456.71 ; -523,4110.19 ccw(c-515,4110.19) -520.66,4104.53 ; -523,4110.19 ccw(c-515,4110.19) -520.66,4104.53 ; -523,4110.19 -523,4149.44 cw(c-515,4165) -497.5,4165 cw(c-515,4165) -507,4149.44 -507,4113.5 -504.15,4110.66 ; -504.34,3744.15 ccw(c-510,3749.81) -502,3749.81 ; -504.34,3744.15 ccw(c-510,3749.81) -502,3749.81 ; -504.15,4110.66 cw(c-509.81,4105) -501.81,4105 ; -504.15,4110.66 cw(c-509.81,4105) -501.81,4105 ; -439.34,4684.19 ccw(c-445,4689.85) -437,4689.85 ; -439.34,4684.19 ccw(c-445,4689.85) -437,4689.85 ; -439.34,4684.19 -493.15,4630.39 cw(c-509.81,4625.04) -492.31,4625.04 cw(c-509.81,4625.04) -504.46,4641.7 -453,4693.16 -453,4779.44 cw(c-445,4795) -427.5,4795 cw(c-445,4795) -437,4779.44 -437,4689.85 ; -422.92,1456.71 ccw(c-422.92,1464.71) -417.26,1459.05 ; -422.92,1456.71 ccw(c-422.92,1464.71) -417.26,1459.05 ; -417.26,1459.05 -389.31,1487 -88.31,1487 277,1121.69 277,905.56 ccw(c285,890) 302.5,890 ccw(c285,890) 293,905.56 293,1125 ; -398.28,1500.66 cw(c-392.62,1495) -392.62,1503 ; -398.28,1500.66 cw(c-392.62,1495) -392.62,1503 ; -392.62,1503 -85,1503 ; -335,4958 cw(c-335,4950) -329.34,4955.66 ; -335,4958 cw(c-335,4950) -329.34,4955.66 ; -314.44,5008 cw(c-314.44,5000) -308.78,5005.66 ; -314.43,5008 cw(c-314.43,5000) -308.78,5005.66 ; -314.44,5008 -338.04,5008 ccw(c-349.76,5005.91) -349.76,5017.81 -428.5,5017.81 ccw(c-428.5,5005.91) -440.41,5005.91 -440.41,4994.09 ccw(c-428.5,4994.09) -428.5,4982.19 -349.76,4982.19 ccw(c-349.76,4994.09) -338.04,4992 -317.75,4992 -300.09,4974.34 ; -308.78,5005.66 -291.12,4988 -280.56,4988 cw(c-265,4980) -247.5,4980 cw(c-265,4980) -280.56,4972 -294.44,4972 ; -300.09,4974.34 ccw(c-294.44,4980) -294.44,4972 ; -300.09,4974.34 ccw(c-294.44,4980) -294.44,4972 ; -233.09,3194.34 ccw(c-227.44,3200) -227.44,3192 ; -233.09,3194.34 ccw(c-227.44,3200) -227.44,3192 ; -233.09,3194.34 -287.79,3249.05 cw(c-293.14,3265.71) -275.64,3265.71 cw(c-293.14,3265.71) -276.48,3260.36 -224.12,3208 -40,3208 ; -227.44,3192 -43.31,3192 152.86,2995.83 152.86,2907.27 ccw(c160.86,2891.71) 178.36,2891.71 ccw(c160.86,2891.71) 168.86,2907.27 168.86,2999.14 ; -167.81,3305 ccw(c-159.81,3305) -165.47,3299.34 ; -167.81,3305 ccw(c-159.81,3305) -165.47,3299.34 ; -167.81,3305 -167.81,3544.3 cw(c-159.81,3559.86) -142.31,3559.86 cw(c-159.81,3559.86) -151.81,3544.3 -151.81,3308.31 -118.2,3274.71 83.29,3274.71 ; -165.47,3299.34 -127.17,3261.05 ; -127.17,3261.05 ccw(c-121.52,3266.71) -121.52,3258.71 ; -127.17,3261.05 ccw(c-121.52,3266.71) -121.52,3258.71 ; -121.52,3258.71 79.98,3258.71 273.86,3064.83 273.86,1815.23 219.34,1760.72 ; -85,1503 cw(c-85,1495) -79.34,1500.66 ; -85,1503 cw(c-85,1495) -79.34,1500.66 ; -79.34,1500.66 290.66,1130.66 ; -40,3208 cw(c-40,3200) -34.34,3205.66 ; -40,3208 cw(c-40,3200) -34.34,3205.66 ; -34.34,3205.66 166.51,3004.8 ; 83.29,3274.71 cw(c83.29,3266.71) 88.95,3272.36 ; 83.29,3274.71 cw(c83.29,3266.71) 88.95,3272.36 ; 88.95,3272.36 287.51,3073.8 ; 117,4284.85 cw(c125,4284.85) 119.34,4290.51 ; 117,4284.85 cw(c125,4284.85) 119.34,4290.51 ; 117,4284.85 117,3560.43 95.28,3538.71 ccw(c76.12,3508.23) 112.12,3508.23 ccw(c76.12,3508.23) 106.6,3527.4 130.66,3551.46 ; 119.34,4290.51 288.85,4460.02 288.85,4576.85 ; 130.66,3551.46 ccw(c125,3557.11) 133,3557.11 ; 130.66,3551.46 ccw(c125,3557.11) 133,3557.11 ; 133,3557.11 133,4281.54 302.51,4451.05 ; 166.51,3004.8 cw(c160.86,2999.14) 168.86,2999.14 ; 166.51,3004.8 cw(c160.86,2999.14) 168.86,2999.14 ; 217,1410 ccw(c225,1410) 219.34,1404.34 ; 217,1410 ccw(c225,1410) 219.34,1404.34 ; 217,1410 217,1755.06 ; 217,1755.06 cw(c225,1755.06) 219.34,1760.72 ; 217,1755.06 cw(c225,1755.06) 219.34,1760.72 ; 219.34,1404.34 338.34,1285.35 ccw(c355,1280) 372.5,1280 ccw(c355,1280) 349.65,1296.66 233,1413.31 233,1751.75 287.51,1806.26 ; 287.51,1806.26 ccw(c281.86,1811.92) 289.86,1811.92 ; 287.51,1806.26 ccw(c281.86,1811.92) 289.86,1811.92 ; 287.51,3073.8 cw(c281.86,3068.14) 289.86,3068.14 ; 287.51,3073.8 cw(c281.86,3068.14) 289.86,3068.14 ; 288.85,4576.85 cw(c296.85,4576.85) 291.2,4582.51 ; 288.85,4576.85 cw(c296.85,4576.85) 291.2,4582.51 ; 289.86,1811.92 289.86,3068.14 ; 290.66,1130.66 cw(c285,1125) 293,1125 ; 290.66,1130.66 cw(c285,1125) 293,1125 ; 291.2,4582.51 303.34,4594.65 cw(c320,4600) 337.5,4600 cw(c320,4600) 314.65,4583.34 304.85,4573.54 304.85,4456.7 ; 302.51,4451.05 ccw(c296.85,4456.7) 304.85,4456.7 ; 302.51,4451.05 ccw(c296.85,4456.7) 304.85,4456.7 ; 402,2810 ccw(c410,2810) 404.34,2804.34 ; 402,2810 ccw(c410,2810) 404.34,2804.34 ; 402,2810 402,3129.52 ; 402,3129.52 cw(c410,3129.52) 404.34,3135.17 ; 402,3129.52 cw(c410,3129.52) 404.34,3135.17 ; 404.34,2804.34 622,2586.69 622,1170 622,955.57 ; 404.34,3135.17 513.46,3244.29 cw(c530,3250) 547.5,3250 cw(c530,3250) 525.02,3233.22 418,3126.2 418,2813.31 635.66,2595.66 ; 622,955.57 ccw(c630,955.57) 624.34,949.91 ; 622,955.57 ccw(c630,955.57) 624.34,949.91 ; 624.34,949.91 1049.34,524.91 ; 635.66,2595.66 cw(c630,2590) 638,2590 ; 635.66,2595.66 cw(c630,2590) 638,2590 ; 638,2590 638,1173.31 638,958.88 1058.31,538.57 1780,538.57 ; 790.92,415.59 ccw(c753.43,415.59) 715.93,415.59 715.93,360.47 ccw(c753.43,360.47) 790.92,360.47 790.92,415.59 ; 1019.08,393.94 cw(c1056.57,393.94) 1094.07,393.94 1094.07,358.5 cw(c1056.57,358.5) 1019.08,358.5 1019.08,393.94 ; 1049.34,524.91 ccw(c1055,530.57) 1055,522.57 ; 1049.34,524.91 ccw(c1055,530.57) 1055,522.57 ; 1055,522.57 1776.69,522.57 1858.57,440.68 1858.57,430.57 ccw(c1866.57,393.94) 1829.08,393.94 ; 1120.93,232.52 cw(c1158.43,232.52) 1195.92,232.52 1195.92,197.09 cw(c1158.43,197.09) 1120.93,197.09 1120.93,232.52 ; 1120.93,415.59 cw(c1158.43,415.59) 1195.92,415.59 ; 1120.93,415.59 1120.93,360.47 ccw(c1158.43,360.47) 1195.92,360.47 1195.92,415.59 ; 1424.08,279.76 cw(c1461.57,279.76) 1499.07,279.76 1499.07,244.33 cw(c1461.57,244.33) 1424.08,244.33 1424.08,279.76 ; 1424.08,393.94 cw(c1461.57,393.94) 1499.07,393.94 1499.07,358.5 cw(c1461.57,358.5) 1424.08,358.5 1424.08,393.94 ; 1525.93,415.59 cw(c1563.43,415.59) 1600.92,415.59 ; 1525.93,415.59 1525.93,360.47 ccw(c1563.43,360.47) 1600.92,360.47 1600.92,415.59 ; 1650.88,3189.4 cw(c1658.88,3189.4) 1652,3193.48 ; 1650.88,3189.4 cw(c1658.88,3189.4) 1652,3193.48 ; 1652,3193.48 1652,3254.44 cw(c1660,3270) 1677.5,3270 cw(c1660,3270) 1668,3254.44 1668,3190.52 ; 1666.88,3186.44 ccw(c1660,3190.52) 1668,3190.52 ; 1666.88,3186.44 ccw(c1660,3190.52) 1668,3190.52 ; 1666.88,3186.44 1666.88,3132.55 cw(c1663.88,3121.97) 1674.63,3124.31 cw(c1685.38,3121.97) 1682.38,3132.55 1682.38,3155.19 ; 1682.38,3155.19 cw(c1690.38,3155.19) 1684.72,3160.84 ; 1682.38,3155.19 cw(c1690.38,3155.19) 1684.72,3160.84 ; 1780,538.57 cw(c1780,530.57) 1785.66,536.23 ; 1780,538.57 cw(c1780,530.57) 1785.66,536.23 ; 1785.66,536.23 1872.23,449.65 ; 1829.08,393.94 1829.08,358.5 ccw(c1866.57,358.5) 1904.07,358.5 1904.07,393.94 ccw(c1866.57,393.94) 1874.57,430.57 1874.57,443.99 ; 1872.23,449.65 cw(c1866.57,443.99) 1874.57,443.99 ; 1872.23,449.65 cw(c1866.57,443.99) 1874.57,443.99 ; 1930.93,232.52 cw(c1968.43,232.52) 2005.92,232.52 2005.92,197.09 cw(c1968.43,197.09) 1930.93,197.09 1930.93,232.52 ; 1930.93,415.59 cw(c1968.43,415.59) 2005.92,415.59 ; 1930.93,415.59 1930.93,360.47 ccw(c1968.43,360.47) 2005.92,360.47 2005.92,415.59 ; 2234.08,279.76 cw(c2271.57,279.76) 2309.07,279.76 2309.07,244.33 cw(c2271.57,244.33) 2234.08,244.33 2234.08,279.76 ; 2234.08,393.94 cw(c2271.57,393.94) 2309.07,393.94 2309.07,358.5 cw(c2271.57,358.5) 2234.08,358.5 2234.08,393.94 ; -577.5,2345 ccw(c-595,2345) -577.5,2345 ; -362.5,3940 ccw(c-380,3940) -362.5,3940 ; -350.64,4308.37 ccw(c-368.14,4308.37) -350.64,4308.37 ; -337.5,4020 ccw(c-355,4020) -337.5,4020 ; -247.5,5050 ccw(c-265,5050) -247.5,5050 ; -237.5,3670 ccw(c-255,3670) -237.5,3670 ; -232.5,3760 ccw(c-250,3760) -232.5,3760 ; -217.5,4925 ccw(c-235,4925) -217.5,4925 ; -162.5,4460 ccw(c-180,4460) -162.5,4460 ; -139,4095 ccw(c-156.5,4095) -139,4095 ; -108.98,5216.71 ccw(c-126.48,5216.71) -108.98,5216.71 ; -108.64,5267.04 ccw(c-126.14,5267.04) -108.64,5267.04 ; -107.5,5105 ccw(c-125,5105) -107.5,5105 ; -97.5,4135 ccw(c-115,4135) -97.5,4135 ; -56.98,2139.71 ccw(c-74.48,2139.71) -56.98,2139.71 ; -32.5,3920 ccw(c-50,3920) -32.5,3920 ; -17.5,3790 ccw(c-35,3790) -17.5,3790 ; v1@-0.64,2901.71 ccw(c-18.14,2901.71) v1@-0.64,2901.71 ; 7.69,2658.37 ccw(c-9.81,2658.37) 7.69,2658.37 ; 37.69,2368.71 ccw(c20.19,2368.71) 37.69,2368.71 ; 57.69,858.37 ccw(c40.19,858.37) 57.69,858.37 ; 91.02,5025.04 ccw(c73.52,5025.04) 91.02,5025.04 ; 112.12,3408.23 ccw(c76.12,3408.23) 112.12,3408.23 ; v1@178.36,2800.04 ccw(c160.86,2800.04) v1@178.36,2800.04 ; 199.36,4950.04 ccw(c181.86,4950.04) 199.36,4950.04 ; 247.5,1285 ccw(c230,1285) 247.5,1285 ; 257.5,5015 ccw(c240,5015) 257.5,5015 ; 347.5,4675 ccw(c330,4675) 347.5,4675 ; 707.69,2725.04 ccw(c690.19,2725.04) 707.69,2725.04 ; 782.5,2575 ccw(c765,2575) 782.5,2575 ; 797.5,4555 ccw(c780,4555) 797.5,4555 ; 1099.36,991.71 ccw(c1081.86,991.71) 1099.36,991.71 ; 1167.36,4635.71 ccw(c1149.86,4635.71) 1167.36,4635.71 ; 1292.5,860 ccw(c1275,860) 1292.5,860 ; 1374.36,991.71 ccw(c1356.86,991.71) 1374.36,991.71
  Top Layer w12: U26.8@-389.13,4850 -200,4850 v1(-175,4875) ; U26.1@-389.13,5200 -306.18,5200 -281.14,5225.04 v1(-243.14,5225.04) ; U26.8@-351.56,4845.89 cw(c-341.64,4835.97) -341.64,4850 cw(c-341.64,4864.03) U26.8@-351.56,4854.11 ; U26.1@-351.56,5195.89 cw(c-341.64,5185.97) -341.64,5200 cw(c-341.64,5214.03) U26.1@-351.56,5204.11 ; v1@-247.03,5221.15 ccw(c-256.42,5211.76) -256.42,5225.04 ccw(c-256.42,5238.32) v1@-247.03,5228.93 ; v1@-180.5,4875 cw(c-193.78,4875) -184.39,4865.61 cw(c-175,4856.22) v1@-175,4869.5 ; v1@-130.36,2712.26 ccw(c-139.75,2721.65) -126.48,2721.65 ccw(c-113.2,2721.65) v1@-122.59,2712.26 ; v1(-126.48,2708.37) -126.48,2728.52 -120,2735 -80.63,2735 U1.20@-79.84,2734.21 ; v1@109.69,5625.04 cw(c96.41,5625.04) 105.8,5615.65 cw(c115.19,5606.26) v1@115.19,5619.54 ; v1(115.19,5625.04) 85,5594.85 85,5110 210,4985 496.9,4985 575,4906.9 575,4680 155,4260 155,3480 190,3445 190,3385 331.86,3243.14 331.86,3128.14 v1(331.86,2766.71) ; v1@327.97,2770.6 ccw(c318.58,2779.99) 331.86,2779.99 ccw(c345.14,2779.99) v1@335.75,2770.6 ; v1(720.52,2634.71) 800.29,2634.71 815,2620 900,2535 900,850 1110,640 v1(1110,575) ; v1@724.41,2630.82 cw(c733.8,2621.43) 733.8,2634.71 cw(c733.8,2647.99) v1@724.41,2638.6 ; v1@1106.11,578.89 ccw(c1096.72,588.28) 1110,588.28 ccw(c1123.28,588.28) v1@1113.89,578.89 ; v1@1106.11,591.11 cw(c1096.72,581.72) 1110,581.72 cw(c1123.28,581.72) v1@1113.89,591.11 ; v1@1106.11,598.89 ccw(c1096.72,608.28) 1110,608.28 ccw(c1123.28,608.28) v1@1113.89,598.89 ; v1@1106.11,611.11 cw(c1096.72,601.72) 1110,601.72 cw(c1123.28,601.72) v1@1113.89,611.11 ; v1@1106.11,618.89 ccw(c1096.72,628.28) 1110,628.28 ccw(c1123.28,628.28) v1@1113.89,618.89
